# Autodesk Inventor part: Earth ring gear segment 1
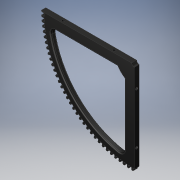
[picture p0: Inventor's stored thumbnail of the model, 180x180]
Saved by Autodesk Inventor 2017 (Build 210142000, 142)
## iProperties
Created: 2016-08
Part Number: Earth ring gear segment 1
Material: Generic
Document SubType Name: Modeling
Designer: Stan
Density: 1 g/cm^3
Appearance: Glossy - Black
Author: Stan
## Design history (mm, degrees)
sketch "Sketch1"
  geometry: L1 (0, -115.696)-(0, -3.175); L2 (-119.081, 0)-(-3.175, 0); L3 (-12.7, -21.997)-(-12.7, -99.798); L4 (-99.798, -12.7)-(-21.997, -12.7); A1 r 1.272 centre (-117.809, 0) between (-119.081, 0) and (-118.123, -1.232); A2 r 27.123 centre (-112.999, 25.402) between (-118.123, -1.232) and (-115.686, -1.587); A3 r 1.272 centre (-117.68, -5.522) between (-118.051, -4.306) and (-117.936, -6.768); A4 r 27.123 centre (-114.065, 20.078) between (-117.936, -6.768) and (-115.484, -7.008); A5 r 27.123 centre (-111.684, -30.671) between (-115.633, -3.837) and (-118.051, -4.306); A6 r 1.272 centre (-117.291, -11.032) between (-117.72, -9.834) and (-117.489, -12.288); A7 r 27.123 centre (-114.881, 14.709) between (-117.489, -12.288) and (-115.029, -12.413); A8 r 27.123 centre (-110.123, -35.872) between (-115.326, -9.252) and (-117.72, -9.834); A9 r 1.272 centre (-116.645, -16.517) between (-117.129, -15.341) and (-116.784, -17.782); A10 r 27.123 centre (-115.444, 9.308) between (-116.784, -17.782) and (-114.32, -17.791); A11 r 27.123 centre (-108.321, -40.994) between (-114.765, -14.648) and (-117.129, -15.341); A12 r 1.272 centre (-115.743, -21.967) between (-116.282, -20.815) and (-115.822, -23.236); A13 r 27.123 centre (-115.753, 3.887) between (-115.822, -23.236) and (-113.361, -23.13); A14 r 27.123 centre (-106.281, -46.026) between (-113.953, -20.011) and (-116.282, -20.815); A15 r 1.272 centre (-114.586, -27.368) between (-115.178, -26.242) and (-114.606, -28.639); A16 r 27.123 centre (-115.808, -1.543) between (-114.606, -28.639) and (-112.152, -28.418); A17 r 27.123 centre (-104.006, -50.957) between (-112.89, -25.33) and (-115.178, -26.242); A18 r 1.272 centre (-113.177, -32.708) between (-113.822, -31.612) and (-113.137, -33.98); A19 r 27.123 centre (-115.609, -6.97) between (-113.137, -33.98) and (-110.697, -33.644); A20 r 27.123 centre (-101.504, -55.776) between (-111.578, -30.594) and (-113.822, -31.612); A21 r 1.272 centre (-111.52, -37.977) between (-112.215, -36.912) and (-111.42, -39.245); A22 r 27.123 centre (-115.155, -12.381) between (-111.42, -39.245) and (-108.998, -38.796); A23 r 27.123 centre (-98.778, -60.473) between (-110.022, -35.79) and (-112.215, -36.912); A24 r 1.272 centre (-109.617, -43.163) between (-110.361, -42.131) and (-109.458, -44.425); A25 r 27.123 centre (-114.448, -17.765) between (-109.458, -44.425) and (-107.06, -43.862); A26 r 27.123 centre (-95.835, -65.036) between (-108.223, -40.908) and (-110.361, -42.131); A27 r 1.272 centre (-107.474, -48.253) between (-108.265, -47.258) and (-107.256, -49.506); A28 r 27.123 centre (-113.49, -23.11) between (-107.256, -49.506) and (-104.886, -48.832); A29 r 27.123 centre (-92.681, -69.457) between (-106.187, -45.935) and (-108.265, -47.258); A30 r 1.272 centre (-105.094, -53.238) between (-105.931, -52.281) and (-104.817, -54.479); A31 r 27.123 centre (-112.282, -28.404) between (-104.817, -54.479) and (-102.482, -53.694); A32 r 27.123 centre (-89.323, -73.724) between (-103.917, -50.862) and (-105.931, -52.281); A33 r 1.272 centre (-102.483, -58.105) between (-103.364, -57.188) and (-102.149, -59.332); A34 r 27.123 centre (-110.827, -33.636) between (-102.149, -59.332) and (-99.853, -58.439); A35 r 27.123 centre (-85.77, -77.83) between (-101.419, -55.677) and (-103.364, -57.188); A36 r 1.272 centre (-99.647, -62.845) between (-100.57, -61.971) and (-99.255, -64.055); A37 r 27.123 centre (-109.129, -38.793) between (-99.255, -64.055) and (-97.004, -63.055); A38 r 27.123 centre (-82.027, -81.765) between (-98.697, -60.37) and (-100.57, -61.971); A39 r 1.272 centre (-96.591, -67.447) between (-97.555, -66.616) and (-96.144, -68.637); A40 r 27.123 centre (-107.19, -43.866) between (-96.144, -68.637) and (-93.942, -67.533); A41 r 27.123 centre (-78.105, -85.52) between (-95.759, -64.929) and (-97.555, -66.616); A42 r 1.272 centre (-93.324, -71.9) between (-94.325, -71.116) and (-92.821, -73.068); A43 r 27.123 centre (-105.016, -48.842) between (-92.821, -73.068) and (-90.673, -71.862); A44 r 27.123 centre (-74.01, -89.087) between (-92.611, -69.347) and (-94.325, -71.116); A45 r 1.272 centre (-89.851, -76.195) between (-90.888, -75.459) and (-89.294, -77.339); A46 r 27.123 centre (-102.612, -53.71) between (-89.294, -77.339) and (-87.205, -76.033); A47 r 27.123 centre (-69.753, -92.458) between (-89.258, -73.611) and (-90.888, -75.459); A48 r 1.272 centre (-86.181, -80.323) between (-87.251, -79.636) and (-85.571, -81.439); A49 r 27.123 centre (-99.981, -58.461) between (-85.571, -81.439) and (-83.545, -80.037); A50 r 27.123 centre (-65.343, -95.626) between (-85.71, -77.714) and (-87.251, -79.636); A51 r 1.272 centre (-82.321, -84.274) between (-83.423, -83.638) and (-81.66, -85.36); A52 r 27.123 centre (-97.131, -63.083) between (-81.66, -85.36) and (-79.702, -83.865); A53 r 27.123 centre (-60.789, -98.583) between (-81.973, -81.646) and (-83.423, -83.638); A54 r 1.272 centre (-78.281, -88.04) between (-79.411, -87.456) and (-77.569, -89.094); A55 r 27.123 centre (-94.068, -67.567) between (-77.569, -89.094) and (-75.683, -87.508); A56 r 27.123 centre (-56.101, -101.324) between (-78.056, -85.399) and (-79.411, -87.456); A57 r 1.272 centre (-74.068, -91.613) between (-75.224, -91.082) and (-73.307, -92.632); A58 r 27.123 centre (-90.797, -71.901) between (-73.307, -92.632) and (-71.499, -90.959); A59 r 27.123 centre (-51.29, -103.843) between (-73.967, -88.963) and (-75.224, -91.082); A60 r 1.272 centre (-69.693, -94.984) between (-70.872, -94.508) and (-68.885, -95.966); A61 r 27.123 centre (-87.327, -76.078) between (-68.885, -95.966) and (-67.156, -94.211); A62 r 27.123 centre (-46.366, -106.133) between (-69.716, -92.333) and (-70.872, -94.508); A63 r 1.272 centre (-65.164, -98.146) between (-66.364, -97.726) and (-64.311, -99.09); A64 r 27.123 centre (-83.665, -80.088) between (-64.311, -99.09) and (-62.667, -97.255)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; 3 further points
  constraints: 206 point on circle, 103 centre point, 8 end point, 2 point on line, 2 tangent, 1 equal radius, 1 horizontal, 1 vertical, 115 other
  dimensions: "d4" = 6.35 radius of A102 (derived)
extrude "Extrusion1" new body sketch "Sketch1" distance "d0" = 6.35; taper "d1" = 0 deg
sketch "Sketch2"
  geometry: L1 (0, 69.804)-(6.35, 69.804) reference; L2 (0, -7.997)-(6.35, -7.997) reference; L3 (6.35, 69.804)-(6.35, -7.997) reference; C1 r 1.587 at (3.175, 63.454); C2 r 1.587 at (3.175, -1.647); 1 further point
  constraints: 2 centre point
  dimensions: "d5" = 6.35 distance from line of C1.centre L1; "d6" = 6.35 distance from line of C2.centre L2; "d7" = 3.175 distance from line of C1.centre L3; "d8" = 3.175 distance from line of C2.centre L3; "d9" = 3.175 diameter of C1; "d10" = 3.175 diameter of C2
extrude "Extrusion2" cut sketch "Sketch2" distance "d11" = 12.7; taper "d12" = 0 deg
sketch "Sketch3"
  geometry: L1 (0, 0)-(0, 6.35) reference; L2 (77.801, 0)-(77.801, 6.35) reference; L3 (0, 6.35)-(77.801, 6.35) reference; C1 r 1.587 at (6.35, 3.175); C2 r 1.587 at (71.451, 3.175); 1 further point
  constraints: 2 centre point
  dimensions: "d13" = 3.175 diameter of C1; "d14" = 3.175 diameter of C2; "d15" = 6.35 distance from line of C1.centre L1; "d16" = 6.35 distance from line of C2.centre L2; "d17" = 3.175 distance from line of C2.centre L3; "d18" = 3.175 distance from line of C1.centre L3
extrude "Extrusion3" cut sketch "Sketch3" distance "d19" = 12.7; taper "d20" = 0 deg
fillet "Fillet1" dims "d23" = 0.79375
fillet "Fillet2" dims "d24" = 0.79375
fillet "Fillet3" dims "d25" = 0.79375
fillet "Fillet4" dims "d26" = 0.79375
fillet "Fillet5" dims "d27" = 0.79375
fillet "Fillet6" dims "d28" = 0.79375
fillet "Fillet7" dims "d29" = 0.79375
fillet "Fillet8" dims "d30" = 1.5875
body "Solid1"
